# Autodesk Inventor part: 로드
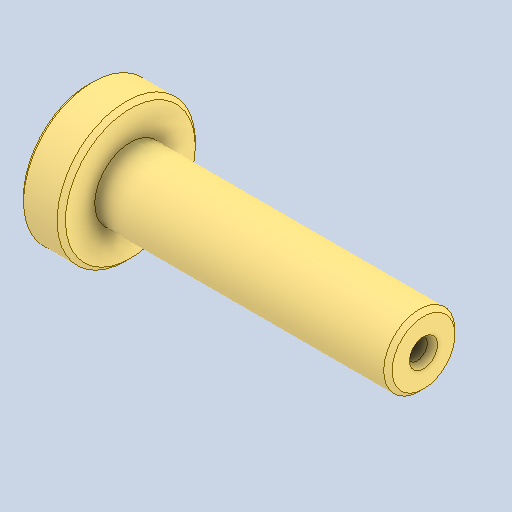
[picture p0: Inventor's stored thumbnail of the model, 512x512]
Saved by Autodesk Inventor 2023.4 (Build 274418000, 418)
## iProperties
Created: 2024-09
Part Number: 로드
Material: 강철, 탄소
Document SubType Name: Modeling
Designer: EDU
Density: 7.85 g/cm^3
Appearance: 기본값
Author: jhkim
Sending System: Autodesk Inventor 2025
Preprocessor: ST-DEVELOPER v20
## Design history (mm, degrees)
feature "솔리드1"
node "솔리드2"
